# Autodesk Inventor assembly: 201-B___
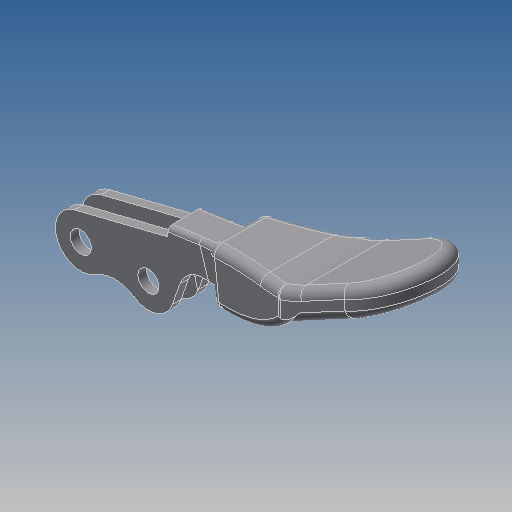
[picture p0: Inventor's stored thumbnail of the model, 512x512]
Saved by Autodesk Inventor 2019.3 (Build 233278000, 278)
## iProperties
Created: 2010-06
Part Number: 201-B___
Material: Ogólny
Document SubType Name: Assembly
Designer: CADENGINEERING4
Author: CADENGINEERING4
Revision Number: ANY
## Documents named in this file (3)
- E:\STRONA\Horizontal toggle clamp\CH-201-BS\201-B___.iam
- E:\STRONA\Horizontal toggle clamp\CH-201-BS\201-B-05___.ipt
- E:\STRONA\Horizontal toggle clamp\CH-201-BS\201-B-03___.ipt
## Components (2 placed, 2 different names)
1. 201-B-05_??_14
2. 201-B-03_??_15
